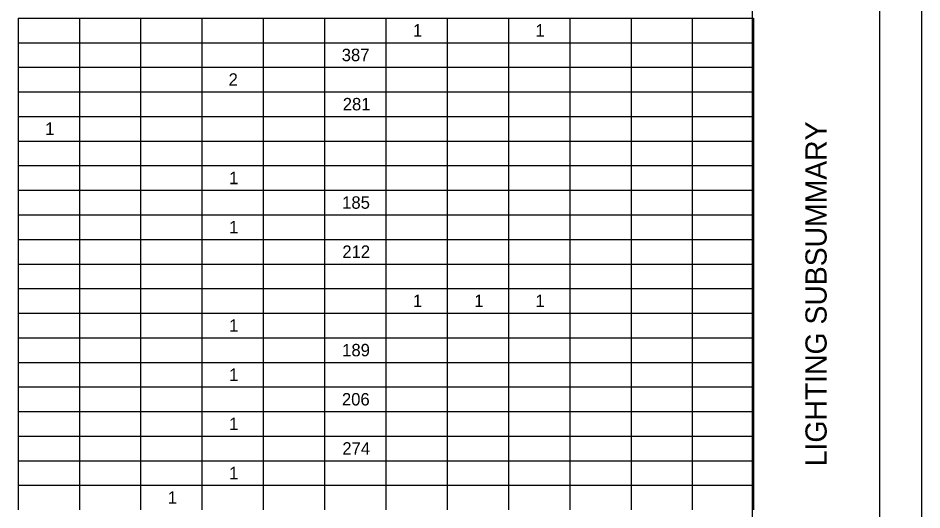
# Model space of a CAD drawing. Extents: x 0 to 34, y 0 to 22.
# Drawn here: x 23.33 to 34, y 10.47 to 16.28 of the extents above; entities that cross this region are included whole.
import ezdxf

# ---------------------------------------------------------------- set-up
doc = ezdxf.new("R2010")
doc.units = 0
for name, color, linetype in [('Default', 7, 'Continuous'), ('SH_Border', 7, 'Continuous'), ('SH_Cut_Line', 7, 'Continuous'), ('SH_Data', 7, 'Continuous')]:
    doc.layers.add(name, color=color, linetype=linetype)

msp = doc.modelspace()

# ---------------------------------------------------------------- linework, layer by layer
at = {"layer": 'Default'}
for p, q in [((23.33, 16.278), (24.054, 16.278)), ((23.33, 16.278), (23.33, 15.987)), ((24.054, 16.278), (26.224, 16.278)), ((24.054, 16.278), (24.054, 15.987)), ((24.777, 16.278), (24.777, 15.987)), ((25.501, 16.278), (25.501, 15.987)), ((26.224, 16.278), (26.948, 16.278)), ((26.224, 16.278), (26.224, 15.987)), ((26.948, 16.278), (27.671, 16.278)), ((26.948, 16.278), (26.948, 15.987)), ((27.671, 16.278), (29.842, 16.278)), ((27.671, 16.278), (27.671, 15.987)), ((28.395, 16.278), (28.395, 15.987)), ((29.119, 16.278), (29.119, 15.987)), ((29.842, 16.278), (30.566, 16.278)), ((29.842, 16.278), (29.842, 15.987)), ((30.566, 16.278), (31.289, 16.278)), ((30.566, 16.278), (30.566, 15.987)), ((31.289, 16.278), (32.013, 16.278)), ((31.289, 16.278), (31.289, 15.987)), ((32.013, 16.278), (32.013, 15.987)), ((23.33, 15.987), (24.054, 15.987)), ((23.33, 15.987), (23.33, 15.697)), ((24.054, 15.987), (26.224, 15.987)), ((24.054, 15.987), (24.054, 15.697)), ((24.777, 15.987), (24.777, 15.697)), ((25.501, 15.987), (25.501, 15.697)), ((26.224, 15.987), (26.948, 15.987)), ((26.224, 15.987), (26.224, 15.697)), ((26.948, 15.987), (27.671, 15.987)), ((26.948, 15.987), (26.948, 15.697)), ((27.671, 15.987), (29.842, 15.987)), ((27.671, 15.987), (27.671, 15.697)), ((28.395, 15.987), (28.395, 15.697)), ((29.119, 15.987), (29.119, 15.697)), ((29.842, 15.987), (30.566, 15.987)), ((29.842, 15.987), (29.842, 15.697)), ((30.566, 15.987), (31.289, 15.987)), ((30.566, 15.987), (30.566, 15.697)), ((31.289, 15.987), (32.013, 15.987)), ((31.289, 15.987), (31.289, 15.697)), ((32.013, 15.987), (32.013, 15.697)), ((23.33, 15.697), (24.054, 15.697)), ((23.33, 15.697), (23.33, 15.407)), ((24.054, 15.697), (26.224, 15.697)), ((24.054, 15.697), (24.054, 15.407)), ((24.777, 15.697), (24.777, 15.407)), ((25.501, 15.697), (25.501, 15.407)), ((26.224, 15.697), (26.948, 15.697)), ((26.224, 15.697), (26.224, 15.407)), ((26.948, 15.697), (27.671, 15.697)), ((26.948, 15.697), (26.948, 15.407)), ((27.671, 15.697), (29.842, 15.697)), ((27.671, 15.697), (27.671, 15.407)), ((28.395, 15.697), (28.395, 15.407)), ((29.119, 15.697), (29.119, 15.407)), ((29.842, 15.697), (30.566, 15.697)), ((29.842, 15.697), (29.842, 15.407)), ((30.566, 15.697), (31.289, 15.697)), ((30.566, 15.697), (30.566, 15.407)), ((31.289, 15.697), (32.013, 15.697)), ((31.289, 15.697), (31.289, 15.407)), ((32.013, 15.697), (32.013, 15.407)), ((23.33, 15.407), (24.054, 15.407)), ((23.33, 15.407), (23.33, 15.117)), ((24.054, 15.407), (26.224, 15.407)), ((24.054, 15.407), (24.054, 15.117)), ((24.777, 15.407), (24.777, 15.117)), ((25.501, 15.407), (25.501, 15.117)), ((26.224, 15.407), (26.948, 15.407)), ((26.224, 15.407), (26.224, 15.117)), ((26.948, 15.407), (27.671, 15.407)), ((26.948, 15.407), (26.948, 15.117)), ((27.671, 15.407), (29.842, 15.407)), ((27.671, 15.407), (27.671, 15.117)), ((28.395, 15.407), (28.395, 15.117)), ((29.119, 15.407), (29.119, 15.117)), ((29.842, 15.407), (30.566, 15.407)), ((29.842, 15.407), (29.842, 15.117)), ((30.566, 15.407), (31.289, 15.407)), ((30.566, 15.407), (30.566, 15.117)), ((31.289, 15.407), (32.013, 15.407)), ((31.289, 15.407), (31.289, 15.117)), ((32.013, 15.407), (32.013, 15.117)), ((23.33, 15.117), (24.054, 15.117)), ((23.33, 15.117), (23.33, 14.827)), ((24.054, 15.117), (26.224, 15.117)), ((24.054, 15.117), (24.054, 14.827)), ((24.777, 15.117), (24.777, 14.827)), ((25.501, 15.117), (25.501, 14.827)), ((26.224, 15.117), (26.948, 15.117)), ((26.224, 15.117), (26.224, 14.827)), ((26.948, 15.117), (27.671, 15.117)), ((26.948, 15.117), (26.948, 14.827)), ((27.671, 15.117), (29.842, 15.117)), ((27.671, 15.117), (27.671, 14.827)), ((28.395, 15.117), (28.395, 14.827)), ((29.119, 15.117), (29.119, 14.827)), ((29.842, 15.117), (30.566, 15.117)), ((29.842, 15.117), (29.842, 14.827)), ((30.566, 15.117), (31.289, 15.117)), ((30.566, 15.117), (30.566, 14.827)), ((31.289, 15.117), (32.013, 15.117)), ((31.289, 15.117), (31.289, 14.827)), ((32.013, 15.117), (32.013, 14.827)), ((23.33, 14.827), (24.054, 14.827)), ((23.33, 14.827), (23.33, 14.537)), ((24.054, 14.827), (26.224, 14.827)), ((24.054, 14.827), (24.054, 14.537)), ((24.777, 14.827), (24.777, 14.537)), ((25.501, 14.827), (25.501, 14.537)), ((26.224, 14.827), (26.948, 14.827)), ((26.224, 14.827), (26.224, 14.537)), ((26.948, 14.827), (27.671, 14.827)), ((26.948, 14.827), (26.948, 14.537)), ((27.671, 14.827), (29.842, 14.827)), ((27.671, 14.827), (27.671, 14.537)), ((28.395, 14.827), (28.395, 14.537)), ((29.119, 14.827), (29.119, 14.537)), ((29.842, 14.827), (30.566, 14.827)), ((29.842, 14.827), (29.842, 14.537)), ((30.566, 14.827), (31.289, 14.827)), ((30.566, 14.827), (30.566, 14.537)), ((31.289, 14.827), (32.013, 14.827)), ((31.289, 14.827), (31.289, 14.537)), ((32.013, 14.827), (32.013, 14.537)), ((23.33, 14.537), (24.054, 14.537)), ((23.33, 14.537), (23.33, 14.247)), ((24.054, 14.537), (26.224, 14.537)), ((24.054, 14.537), (24.054, 14.247)), ((24.777, 14.537), (24.777, 14.247)), ((25.501, 14.537), (25.501, 14.247)), ((26.224, 14.537), (26.948, 14.537)), ((26.224, 14.537), (26.224, 14.247)), ((26.948, 14.537), (27.671, 14.537)), ((26.948, 14.537), (26.948, 14.247)), ((27.671, 14.537), (29.842, 14.537)), ((27.671, 14.537), (27.671, 14.247)), ((28.395, 14.537), (28.395, 14.247)), ((29.119, 14.537), (29.119, 14.247)), ((29.842, 14.537), (30.566, 14.537)), ((29.842, 14.537), (29.842, 14.247)), ((30.566, 14.537), (31.289, 14.537)), ((30.566, 14.537), (30.566, 14.247)), ((31.289, 14.537), (32.013, 14.537)), ((31.289, 14.537), (31.289, 14.247)), ((32.013, 14.537), (32.013, 14.247)), ((23.33, 14.247), (24.054, 14.247)), ((23.33, 14.247), (23.33, 13.956)), ((24.054, 14.247), (26.224, 14.247)), ((24.054, 14.247), (24.054, 13.956)), ((24.777, 14.247), (24.777, 13.956)), ((25.501, 14.247), (25.501, 13.956)), ((26.224, 14.247), (26.948, 14.247)), ((26.224, 14.247), (26.224, 13.956)), ((26.948, 14.247), (27.671, 14.247)), ((26.948, 14.247), (26.948, 13.956)), ((27.671, 14.247), (29.842, 14.247)), ((27.671, 14.247), (27.671, 13.956)), ((28.395, 14.247), (28.395, 13.956)), ((29.119, 14.247), (29.119, 13.956)), ((29.842, 14.247), (30.566, 14.247)), ((29.842, 14.247), (29.842, 13.956)), ((30.566, 14.247), (31.289, 14.247)), ((30.566, 14.247), (30.566, 13.956)), ((31.289, 14.247), (32.013, 14.247)), ((31.289, 14.247), (31.289, 13.956)), ((32.013, 14.247), (32.013, 13.956)), ((23.33, 13.956), (24.054, 13.956)), ((23.33, 13.956), (23.33, 13.666)), ((24.054, 13.956), (26.224, 13.956)), ((24.054, 13.956), (24.054, 13.666)), ((24.777, 13.956), (24.777, 13.666)), ((25.501, 13.956), (25.501, 13.666)), ((26.224, 13.956), (26.948, 13.956)), ((26.224, 13.956), (26.224, 13.666)), ((26.948, 13.956), (27.671, 13.956)), ((26.948, 13.956), (26.948, 13.666)), ((27.671, 13.956), (29.842, 13.956)), ((27.671, 13.956), (27.671, 13.666)), ((28.395, 13.956), (28.395, 13.666)), ((29.119, 13.956), (29.119, 13.666)), ((29.842, 13.956), (30.566, 13.956)), ((29.842, 13.956), (29.842, 13.666)), ((30.566, 13.956), (31.289, 13.956)), ((30.566, 13.956), (30.566, 13.666)), ((31.289, 13.956), (32.013, 13.956)), ((31.289, 13.956), (31.289, 13.666)), ((32.013, 13.956), (32.013, 13.666)), ((23.33, 13.666), (24.054, 13.666)), ((23.33, 13.666), (23.33, 13.376)), ((24.054, 13.666), (26.224, 13.666)), ((24.054, 13.666), (24.054, 13.376)), ((24.777, 13.666), (24.777, 13.376)), ((25.501, 13.666), (25.501, 13.376)), ((26.224, 13.666), (26.948, 13.666)), ((26.224, 13.666), (26.224, 13.376)), ((26.948, 13.666), (27.671, 13.666)), ((26.948, 13.666), (26.948, 13.376)), ((27.671, 13.666), (29.842, 13.666)), ((27.671, 13.666), (27.671, 13.376)), ((28.395, 13.666), (28.395, 13.376)), ((29.119, 13.666), (29.119, 13.376)), ((29.842, 13.666), (30.566, 13.666)), ((29.842, 13.666), (29.842, 13.376)), ((30.566, 13.666), (31.289, 13.666)), ((30.566, 13.666), (30.566, 13.376)), ((31.289, 13.666), (32.013, 13.666)), ((31.289, 13.666), (31.289, 13.376)), ((32.013, 13.666), (32.013, 13.376)), ((23.33, 13.376), (24.054, 13.376)), ((23.33, 13.376), (23.33, 13.086)), ((24.054, 13.376), (26.224, 13.376)), ((24.054, 13.376), (24.054, 13.086)), ((24.777, 13.376), (24.777, 13.086)), ((25.501, 13.376), (25.501, 13.086)), ((26.224, 13.376), (26.948, 13.376)), ((26.224, 13.376), (26.224, 13.086)), ((26.948, 13.376), (27.671, 13.376)), ((26.948, 13.376), (26.948, 13.086)), ((27.671, 13.376), (29.842, 13.376)), ((27.671, 13.376), (27.671, 13.086)), ((28.395, 13.376), (28.395, 13.086)), ((29.119, 13.376), (29.119, 13.086)), ((29.842, 13.376), (30.566, 13.376)), ((29.842, 13.376), (29.842, 13.086)), ((30.566, 13.376), (31.289, 13.376)), ((30.566, 13.376), (30.566, 13.086)), ((31.289, 13.376), (32.013, 13.376)), ((31.289, 13.376), (31.289, 13.086)), ((32.013, 13.376), (32.013, 13.086)), ((23.33, 13.086), (24.054, 13.086)), ((23.33, 13.086), (23.33, 12.796)), ((24.054, 13.086), (26.224, 13.086)), ((24.054, 13.086), (24.054, 12.796)), ((24.777, 13.086), (24.777, 12.796)), ((25.501, 13.086), (25.501, 12.796)), ((26.224, 13.086), (26.948, 13.086)), ((26.224, 13.086), (26.224, 12.796)), ((26.948, 13.086), (27.671, 13.086)), ((26.948, 13.086), (26.948, 12.796)), ((27.671, 13.086), (29.842, 13.086)), ((27.671, 13.086), (27.671, 12.796)), ((28.395, 13.086), (28.395, 12.796)), ((29.119, 13.086), (29.119, 12.796)), ((29.842, 13.086), (30.566, 13.086)), ((29.842, 13.086), (29.842, 12.796)), ((30.566, 13.086), (31.289, 13.086)), ((30.566, 13.086), (30.566, 12.796)), ((31.289, 13.086), (32.013, 13.086)), ((31.289, 13.086), (31.289, 12.796)), ((32.013, 13.086), (32.013, 12.796)), ((23.33, 12.796), (24.054, 12.796)), ((23.33, 12.796), (23.33, 12.506)), ((24.054, 12.796), (26.224, 12.796)), ((24.054, 12.796), (24.054, 12.506)), ((24.777, 12.796), (24.777, 12.506)), ((25.501, 12.796), (25.501, 12.506)), ((26.224, 12.796), (26.948, 12.796)), ((26.224, 12.796), (26.224, 12.506)), ((26.948, 12.796), (27.671, 12.796)), ((26.948, 12.796), (26.948, 12.506)), ((27.671, 12.796), (29.842, 12.796)), ((27.671, 12.796), (27.671, 12.506)), ((28.395, 12.796), (28.395, 12.506)), ((29.119, 12.796), (29.119, 12.506)), ((29.842, 12.796), (30.566, 12.796)), ((29.842, 12.796), (29.842, 12.506)), ((30.566, 12.796), (31.289, 12.796)), ((30.566, 12.796), (30.566, 12.506)), ((31.289, 12.796), (32.013, 12.796)), ((31.289, 12.796), (31.289, 12.506)), ((32.013, 12.796), (32.013, 12.506)), ((23.33, 12.506), (24.054, 12.506)), ((23.33, 12.506), (23.33, 12.216)), ((24.054, 12.506), (26.224, 12.506)), ((24.054, 12.506), (24.054, 12.216)), ((24.777, 12.506), (24.777, 12.216)), ((25.501, 12.506), (25.501, 12.216)), ((26.224, 12.506), (26.948, 12.506)), ((26.224, 12.506), (26.224, 12.216)), ((26.948, 12.506), (27.671, 12.506)), ((26.948, 12.506), (26.948, 12.216)), ((27.671, 12.506), (29.842, 12.506)), ((27.671, 12.506), (27.671, 12.216)), ((28.395, 12.506), (28.395, 12.216)), ((29.119, 12.506), (29.119, 12.216)), ((29.842, 12.506), (30.566, 12.506)), ((29.842, 12.506), (29.842, 12.216)), ((30.566, 12.506), (31.289, 12.506)), ((30.566, 12.506), (30.566, 12.216)), ((31.289, 12.506), (32.013, 12.506)), ((31.289, 12.506), (31.289, 12.216)), ((32.013, 12.506), (32.013, 12.216)), ((23.33, 12.216), (24.054, 12.216)), ((23.33, 12.216), (23.33, 11.926)), ((24.054, 12.216), (26.224, 12.216)), ((24.054, 12.216), (24.054, 11.926)), ((24.777, 12.216), (24.777, 11.926)), ((25.501, 12.216), (25.501, 11.926)), ((26.224, 12.216), (26.948, 12.216)), ((26.224, 12.216), (26.224, 11.926)), ((26.948, 12.216), (27.671, 12.216)), ((26.948, 12.216), (26.948, 11.926)), ((27.671, 12.216), (29.842, 12.216)), ((27.671, 12.216), (27.671, 11.926)), ((28.395, 12.216), (28.395, 11.926)), ((29.119, 12.216), (29.119, 11.926)), ((29.842, 12.216), (30.566, 12.216)), ((29.842, 12.216), (29.842, 11.926)), ((30.566, 12.216), (31.289, 12.216)), ((30.566, 12.216), (30.566, 11.926)), ((31.289, 12.216), (32.013, 12.216)), ((31.289, 12.216), (31.289, 11.926)), ((32.013, 12.216), (32.013, 11.926)), ((23.33, 11.926), (24.054, 11.926)), ((23.33, 11.926), (23.33, 11.635)), ((24.054, 11.926), (26.224, 11.926)), ((24.054, 11.926), (24.054, 11.635)), ((24.777, 11.926), (24.777, 11.635)), ((25.501, 11.926), (25.501, 11.635)), ((26.224, 11.926), (26.948, 11.926)), ((26.224, 11.926), (26.224, 11.635)), ((26.948, 11.926), (27.671, 11.926)), ((26.948, 11.926), (26.948, 11.635)), ((27.671, 11.926), (29.842, 11.926)), ((27.671, 11.926), (27.671, 11.635)), ((28.395, 11.926), (28.395, 11.635)), ((29.119, 11.926), (29.119, 11.635)), ((29.842, 11.926), (30.566, 11.926)), ((29.842, 11.926), (29.842, 11.635)), ((30.566, 11.926), (31.289, 11.926)), ((30.566, 11.926), (30.566, 11.635)), ((31.289, 11.926), (32.013, 11.926)), ((31.289, 11.926), (31.289, 11.635)), ((32.013, 11.926), (32.013, 11.635)), ((23.33, 11.635), (24.054, 11.635)), ((23.33, 11.635), (23.33, 11.345)), ((24.054, 11.635), (26.224, 11.635)), ((24.054, 11.635), (24.054, 11.345)), ((24.777, 11.635), (24.777, 11.345)), ((25.501, 11.635), (25.501, 11.345)), ((26.224, 11.635), (26.948, 11.635)), ((26.224, 11.635), (26.224, 11.345)), ((26.948, 11.635), (27.671, 11.635)), ((26.948, 11.635), (26.948, 11.345)), ((27.671, 11.635), (29.842, 11.635)), ((27.671, 11.635), (27.671, 11.345)), ((28.395, 11.635), (28.395, 11.345)), ((29.119, 11.635), (29.119, 11.345)), ((29.842, 11.635), (30.566, 11.635)), ((29.842, 11.635), (29.842, 11.345)), ((30.566, 11.635), (31.289, 11.635)), ((30.566, 11.635), (30.566, 11.345)), ((31.289, 11.635), (32.013, 11.635)), ((31.289, 11.635), (31.289, 11.345)), ((32.013, 11.635), (32.013, 11.345)), ((23.33, 11.345), (24.054, 11.345)), ((23.33, 11.345), (23.33, 11.055)), ((24.054, 11.345), (26.224, 11.345)), ((24.054, 11.345), (24.054, 11.055)), ((24.777, 11.345), (24.777, 11.055)), ((25.501, 11.345), (25.501, 11.055)), ((26.224, 11.345), (26.948, 11.345)), ((26.224, 11.345), (26.224, 11.055)), ((26.948, 11.345), (27.671, 11.345)), ((26.948, 11.345), (26.948, 11.055)), ((27.671, 11.345), (29.842, 11.345)), ((27.671, 11.345), (27.671, 11.055)), ((28.395, 11.345), (28.395, 11.055)), ((29.119, 11.345), (29.119, 11.055)), ((29.842, 11.345), (30.566, 11.345)), ((29.842, 11.345), (29.842, 11.055)), ((30.566, 11.345), (31.289, 11.345)), ((30.566, 11.345), (30.566, 11.055)), ((31.289, 11.345), (32.013, 11.345)), ((31.289, 11.345), (31.289, 11.055)), ((32.013, 11.345), (32.013, 11.055)), ((23.33, 11.055), (24.054, 11.055)), ((23.33, 11.055), (23.33, 10.765)), ((24.054, 11.055), (26.224, 11.055)), ((24.054, 11.055), (24.054, 10.765)), ((24.777, 11.055), (24.777, 10.765)), ((25.501, 11.055), (25.501, 10.765)), ((26.224, 11.055), (26.948, 11.055)), ((26.224, 11.055), (26.224, 10.765)), ((26.948, 11.055), (27.671, 11.055)), ((26.948, 11.055), (26.948, 10.765)), ((27.671, 11.055), (29.842, 11.055)), ((27.671, 11.055), (27.671, 10.765)), ((28.395, 11.055), (28.395, 10.765)), ((29.119, 11.055), (29.119, 10.765)), ((29.842, 11.055), (30.566, 11.055)), ((29.842, 11.055), (29.842, 10.765)), ((30.566, 11.055), (31.289, 11.055)), ((30.566, 11.055), (30.566, 10.765)), ((31.289, 11.055), (32.013, 11.055)), ((31.289, 11.055), (31.289, 10.765)), ((32.013, 11.055), (32.013, 10.765)), ((23.33, 10.765), (24.054, 10.765)), ((23.33, 10.765), (23.33, 10.475)), ((24.054, 10.765), (26.224, 10.765)), ((24.054, 10.765), (24.054, 10.475)), ((24.777, 10.765), (24.777, 10.475)), ((25.501, 10.765), (25.501, 10.475)), ((26.224, 10.765), (26.948, 10.765)), ((26.224, 10.765), (26.224, 10.475)), ((26.948, 10.765), (27.671, 10.765)), ((26.948, 10.765), (26.948, 10.475)), ((27.671, 10.765), (29.842, 10.765)), ((27.671, 10.765), (27.671, 10.475)), ((28.395, 10.765), (28.395, 10.475)), ((29.119, 10.765), (29.119, 10.475)), ((29.842, 10.765), (30.566, 10.765)), ((29.842, 10.765), (29.842, 10.475)), ((30.566, 10.765), (31.289, 10.765)), ((30.566, 10.765), (30.566, 10.475)), ((31.289, 10.765), (32.013, 10.765)), ((31.289, 10.765), (31.289, 10.475)), ((32.013, 10.765), (32.013, 10.475))]:
    msp.add_line(p, q, dxfattribs=at)
at = {"layer": 'SH_Border'}
msp.add_line((32, 0.5), (32, 21.5), dxfattribs=at)
msp.add_lwpolyline([(1.5, 21.5), (33.5, 21.5), (33.5, 0.5), (1.5, 0.5)], close=True, dxfattribs=at)
at = {"layer": 'SH_Cut_Line'}
msp.add_lwpolyline([(0, 0), (34, 0), (34, 22), (0, 22)], close=True, dxfattribs=at)

# ---------------------------------------------------------------- texts
at = {"layer": 'Default'}
for s, height, p in [('1', 0.147, (27.991, 16.059)), ('1', 0.147, (29.438, 16.059)), ('387', 0.1468, (27.151, 15.769)), ('2', 0.147, (25.815, 15.479)), ('281', 0.1468, (27.163, 15.189)), ('1', 0.147, (23.65, 14.899)), ('1', 0.147, (25.821, 14.318)), ('185', 0.1468, (27.156, 14.028)), ('1', 0.147, (25.821, 13.738)), ('212', 0.1468, (27.158, 13.448)), ('1', 0.147, (27.991, 12.868)), ('1', 0.147, (28.715, 12.868)), ('1', 0.147, (29.438, 12.868)), ('1', 0.147, (25.821, 12.577)), ('189', 0.1468, (27.156, 12.287)), ('1', 0.147, (25.821, 11.997)), ('206', 0.1468, (27.153, 11.707)), ('1', 0.147, (25.821, 11.417)), ('274', 0.1468, (27.158, 11.127)), ('1', 0.147, (25.821, 10.837)), ('1', 0.147, (25.097, 10.547))]:
    msp.add_text(s, height=height, dxfattribs=at).set_placement(p)
at = {"layer": 'SH_Data'}
msp.add_text('LIGHTING SUBSUMMARY', height=0.25, rotation=90, dxfattribs=at).set_placement((32.875, 10.99))

doc.saveas('drawing.dxf')
